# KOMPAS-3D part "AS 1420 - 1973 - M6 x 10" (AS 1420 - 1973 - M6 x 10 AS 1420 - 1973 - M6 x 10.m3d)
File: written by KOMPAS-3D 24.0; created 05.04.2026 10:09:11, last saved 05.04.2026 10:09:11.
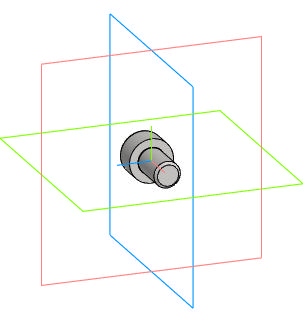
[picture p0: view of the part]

Document properties: Автор: R2D2; Полное имя файла: E:\Работа\Зайцев\Аксессуары для пневмоприводов\Ручной дублер DN.ru\MON3-700-T38-ISO Ручной дублер DN.ru\исходные материалы\AS 1420 - 1973 - M6 x 10 AS 1420 - 1973 - M6 x 10.m3d

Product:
- Body: Solid1  | qty 1
- Part/product: AS 1420 - 1973 - M6 x 10
    Комментарий: Винты с шестигранным   углублением метрические   ISO
    additional columns: Сталь, мягкая

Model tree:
1. Solid1  (labels: Solid1)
